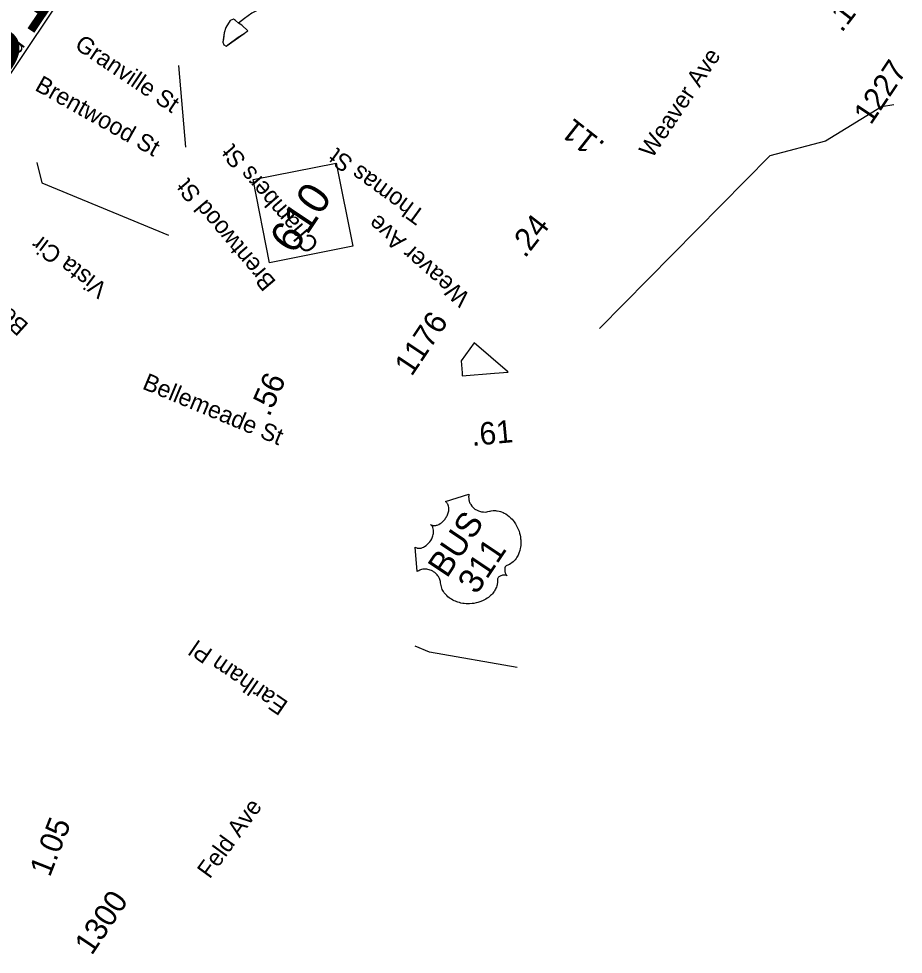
# Model space of a CAD drawing. Extents: x 1716282 to 1717158, y 799307 to 801078.
# Drawn here: x 1716976.7 to 1717048, y 800655.1 to 800730.5 of the extents above; entities that cross this region are included whole.
import ezdxf

# ---------------------------------------------------------------- set-up
doc = ezdxf.new("R2010")
doc.units = 0
for name, color, linetype in [('Exist Boundary Political City Limit New Hole', 7, 'Continuous'), ('Exist Hydrographic Misc Water Feature', 7, 'Continuous'), ('Exist Road Non-System Type 51', 7, 'Continuous'), ('Exist Road Non-System Type 51 Label', 7, 'Continuous'), ('Exist Road Primary Interstate Structure Ovrhead Sign CELL', 7, 'Continuous'), ('Exist Road Primary NC Mileage Hundredths English Label', 7, 'Continuous'), ('Exist Road Primary NC Shield CELL', 7, 'Continuous'), ('Exist Road Primary NC Shield Number Label', 7, 'Continuous'), ('Exist Road Primary US Mileage Hundredths English Label', 7, 'Continuous'), ('Exist Road Primary US Shield CELL', 7, 'Continuous'), ('Exist Road Primary US Shield Number Label', 7, 'Continuous'), ('Exist Road Secondary Mileage Hundredths English Label', 7, 'Continuous'), ('Exist Road Secondary Mileage Tenths English Label', 7, 'Continuous'), ('Exist Road Secondary Type 51 Number Label', 7, 'Continuous')]:
    doc.layers.add(name, color=color, linetype=linetype)

msp = doc.modelspace()

# ---------------------------------------------------------------- linework, layer by layer
at = {"layer": 'Exist Boundary Political City Limit New Hole'}
msp.add_lwpolyline([(1717015.061, 800701.907), (1717016.154, 800701.996), (1717016.081, 800702.06), (1717016.106, 800702.062), (1717013.44, 800704.375), (1717012.374, 800702.905), (1717012.452, 800701.95), (1717012.468, 800701.762), (1717012.474, 800701.693), (1717015.061, 800701.907)], dxfattribs=at)
at = {"layer": 'Exist Hydrographic Misc Water Feature'}
for points in [[(1717006.217, 800745.185), (1717005.764, 800744.265), (1717005.583, 800743.125), (1717005.671, 800742.431), (1717005.92, 800741.665), (1717005.861, 800740.651), (1717005.434, 800738.485), (1717005.165, 800737.473), (1717004.642, 800736.039), (1717003.846, 800734.719), (1717003.113, 800733.955), (1717002.245, 800733.25), (1717001.104, 800732.763), (1717000, 800732.535), (1716998.83, 800732.211), (1716997.53, 800731.798), (1716996.577, 800731.431), (1716995.525, 800730.92), (1716994.916, 800730.494), (1716994.446, 800730.111)], [(1716994.446, 800730.111), (1716994.198, 800730.316), (1716994.031, 800730.43), (1716993.78, 800730.321), (1716993.426, 800729.752), (1716993.279, 800729.329), (1716993.225, 800728.839), (1716993.189, 800728.58), (1716993.251, 800728.364), (1716993.459, 800728.256), (1716993.695, 800728.447), (1716994.408, 800728.977), (1716994.894, 800729.278), (1716995.041, 800729.389), (1716995.186, 800729.499), (1716994.709, 800729.933), (1716994.446, 800730.111)], [(1716994.446, 800730.111), (1716994.198, 800730.316), (1716994.031, 800730.43), (1716993.78, 800730.321), (1716993.426, 800729.752), (1716993.279, 800729.329), (1716993.189, 800728.58), (1716993.251, 800728.364), (1716993.459, 800728.256), (1716994.894, 800729.278), (1716995.041, 800729.389), (1716995.186, 800729.499), (1716994.709, 800729.933), (1716994.446, 800730.111)], [(1717047.219, 800723.53), (1717046.231, 800723.377), (1717041.732, 800720.594), (1717037.245, 800719.41), (1717023.521, 800705.511)], [(1717016.89, 800678.217), (1717009.828, 800679.448), (1717008.667, 800679.945)]]:
    msp.add_lwpolyline(points, dxfattribs=at)
at = {"layer": 'Exist Road Non-System Type 51'}
msp.add_line((1716990.19, 800720.107), (1716989.626, 800726.707), dxfattribs=at)
msp.add_lwpolyline([(1716978.192, 800718.887), (1716978.599, 800717.245), (1716988.819, 800713.026)], dxfattribs=at)
at = {"layer": 'Exist Road Primary Interstate Structure Ovrhead Sign CELL'}
msp.add_lwpolyline([(1716969.549, 800728.043), (1716984.84, 800750.889), (1716990.251, 800747.268), (1716974.959, 800724.421)], close=True, dxfattribs=at)
at = {"layer": 'Exist Road Primary NC Shield CELL'}
msp.add_lwpolyline([(1716996.945, 800710.811), (1716995.618, 800717.509), (1717002.316, 800718.836), (1717003.643, 800712.137)], close=True, dxfattribs=at)
at = {"layer": 'Exist Road Primary US Shield CELL'}
msp.add_lwpolyline([(1717008.682, 800687.905), (1717008.737, 800687.872), (1717008.809, 800687.843), (1717008.848, 800687.831), (1717008.93, 800687.819), (1717009.035, 800687.819), (1717009.153, 800687.838), (1717009.267, 800687.873), (1717009.334, 800687.902), (1717009.44, 800687.958), (1717009.548, 800688.029), (1717009.653, 800688.118), (1717009.751, 800688.216), (1717009.848, 800688.33), (1717009.931, 800688.45), (1717010.01, 800688.588), (1717010.079, 800688.752), (1717010.106, 800688.831), (1717010.131, 800688.923), (1717010.149, 800689.012), (1717010.159, 800689.116), (1717010.161, 800689.203), (1717010.158, 800689.275), (1717010.138, 800689.386), (1717010.107, 800689.485), (1717010.085, 800689.533), (1717010.061, 800689.577), (1717010.002, 800689.656), (1717009.973, 800689.686), (1717009.906, 800689.739), (1717009.968, 800689.704), (1717010.01, 800689.685), (1717010.052, 800689.67), (1717010.101, 800689.66), (1717010.174, 800689.651), (1717010.24, 800689.65), (1717010.345, 800689.662), (1717010.402, 800689.676), (1717010.45, 800689.69), (1717010.568, 800689.737), (1717010.688, 800689.805), (1717010.743, 800689.84), (1717010.796, 800689.879), (1717010.859, 800689.931), (1717010.92, 800689.988), (1717010.976, 800690.047), (1717011.031, 800690.108), (1717011.083, 800690.174), (1717011.123, 800690.23), (1717011.169, 800690.3), (1717011.208, 800690.367), (1717011.244, 800690.438), (1717011.281, 800690.518), (1717011.307, 800690.585), (1717011.338, 800690.676), (1717011.36, 800690.762), (1717011.374, 800690.841), (1717011.386, 800690.949), (1717011.389, 800691.04), (1717011.382, 800691.112), (1717011.368, 800691.202), (1717011.342, 800691.296), (1717011.318, 800691.357), (1717011.287, 800691.41), (1717011.252, 800691.463), (1717011.209, 800691.51), (1717011.169, 800691.546), (1717011.131, 800691.573), (1717013.009, 800692.17), (1717013, 800692.133), (1717012.987, 800692.04), (1717012.983, 800691.963), (1717012.986, 800691.834), (1717012.995, 800691.773), (1717013.005, 800691.711), (1717013.02, 800691.651), (1717013.035, 800691.597), (1717013.061, 800691.525), (1717013.091, 800691.458), (1717013.125, 800691.387), (1717013.159, 800691.33), (1717013.235, 800691.222), (1717013.288, 800691.16), (1717013.335, 800691.11), (1717013.439, 800691.019), (1717013.491, 800690.979), (1717013.545, 800690.943), (1717013.603, 800690.908), (1717013.661, 800690.877), (1717013.725, 800690.848), (1717013.781, 800690.824), (1717013.853, 800690.799), (1717013.939, 800690.774), (1717014.027, 800690.756), (1717014.177, 800690.74), (1717014.341, 800690.739), (1717014.441, 800690.75), (1717014.53, 800690.767), (1717014.65, 800690.801), (1717014.716, 800690.819), (1717014.798, 800690.835), (1717014.945, 800690.853), (1717015.011, 800690.856), (1717015.082, 800690.856), (1717015.153, 800690.852), (1717015.228, 800690.846), (1717015.292, 800690.838), (1717015.431, 800690.81), (1717015.56, 800690.771), (1717015.626, 800690.749), (1717015.768, 800690.689), (1717015.836, 800690.656), (1717015.965, 800690.584), (1717016.114, 800690.485), (1717016.247, 800690.38), (1717016.393, 800690.243), (1717016.477, 800690.156), (1717016.569, 800690.045), (1717016.646, 800689.947), (1717016.753, 800689.79), (1717016.824, 800689.668), (1717016.903, 800689.517), (1717016.947, 800689.421), (1717016.992, 800689.313), (1717017.039, 800689.184), (1717017.085, 800689.04), (1717017.125, 800688.876), (1717017.15, 800688.748), (1717017.173, 800688.589), (1717017.182, 800688.495), (1717017.19, 800688.365), (1717017.189, 800688.194), (1717017.179, 800688.033), (1717017.163, 800687.9), (1717017.142, 800687.787), (1717017.109, 800687.644), (1717017.035, 800687.42), (1717017.003, 800687.342), (1717016.961, 800687.252), (1717016.917, 800687.171), (1717016.872, 800687.094), (1717016.805, 800686.994), (1717016.732, 800686.9), (1717016.655, 800686.815), (1717016.569, 800686.731), (1717016.471, 800686.649), (1717016.372, 800686.581), (1717016.263, 800686.518), (1717016.058, 800686.427), (1717016.003, 800686.397), (1717015.979, 800686.376), (1717015.935, 800686.317), (1717015.908, 800686.251), (1717015.892, 800686.176), (1717015.887, 800686.128), (1717015.887, 800686.06), (1717015.891, 800686.004), (1717015.904, 800685.933), (1717015.918, 800685.879), (1717015.93, 800685.838), (1717015.97, 800685.746), (1717015.993, 800685.708), (1717016.025, 800685.663), (1717016.079, 800685.605), (1717015.985, 800685.639), (1717015.916, 800685.651), (1717015.853, 800685.654), (1717015.794, 800685.653), (1717015.712, 800685.642), (1717015.647, 800685.628), (1717015.575, 800685.606), (1717015.51, 800685.575), (1717015.461, 800685.548), (1717015.421, 800685.52), (1717015.379, 800685.482), (1717015.351, 800685.446), (1717015.331, 800685.414), (1717015.312, 800685.365), (1717015.315, 800685.279), (1717015.316, 800685.199), (1717015.313, 800685.114), (1717015.303, 800685.018), (1717015.293, 800684.95), (1717015.275, 800684.871), (1717015.251, 800684.783), (1717015.219, 800684.69), (1717015.18, 800684.599), (1717015.144, 800684.52), (1717015.1, 800684.439), (1717015.056, 800684.369), (1717015.007, 800684.297), (1717014.957, 800684.234), (1717014.898, 800684.16), (1717014.819, 800684.073), (1717014.747, 800684.005), (1717014.668, 800683.936), (1717014.582, 800683.867), (1717014.484, 800683.798), (1717014.356, 800683.715), (1717014.26, 800683.662), (1717014.101, 800683.583), (1717013.897, 800683.503), (1717013.73, 800683.451), (1717013.599, 800683.419), (1717013.394, 800683.38), (1717013.265, 800683.363), (1717013.045, 800683.347), (1717012.891, 800683.346), (1717012.783, 800683.351), (1717012.613, 800683.366), (1717012.51, 800683.381), (1717012.364, 800683.408), (1717012.235, 800683.44), (1717012.116, 800683.474), (1717012.041, 800683.499), (1717011.915, 800683.548), (1717011.828, 800683.585), (1717011.711, 800683.642), (1717011.593, 800683.71), (1717011.489, 800683.778), (1717011.404, 800683.838), (1717011.31, 800683.915), (1717011.215, 800684.004), (1717011.137, 800684.086), (1717011.083, 800684.148), (1717011.021, 800684.229), (1717010.957, 800684.324), (1717010.9, 800684.423), (1717010.857, 800684.511), (1717010.815, 800684.612), (1717010.784, 800684.705), (1717010.757, 800684.818), (1717010.738, 800684.93), (1717010.729, 800685.026), (1717010.706, 800685.149), (1717010.688, 800685.217), (1717010.657, 800685.304), (1717010.625, 800685.38), (1717010.595, 800685.443), (1717010.546, 800685.532), (1717010.505, 800685.593), (1717010.439, 800685.68), (1717010.388, 800685.735), (1717010.32, 800685.803), (1717010.254, 800685.862), (1717010.164, 800685.927), (1717010.087, 800685.975), (1717009.992, 800686.025), (1717009.896, 800686.065), (1717009.809, 800686.094), (1717009.703, 800686.119), (1717009.621, 800686.132), (1717009.504, 800686.139), (1717009.39, 800686.136), (1717009.289, 800686.123), (1717009.194, 800686.104), (1717009.115, 800686.078), (1717009.043, 800686.051), (1717008.96, 800686.012), (1717008.887, 800685.97), (1717008.845, 800685.941)], close=True, dxfattribs=at)

# ---------------------------------------------------------------- texts
at = {"layer": 'Exist Road Non-System Type 51 Label'}
for s, rotation, p in [('E Springfield Rd', 52.59426, (1716969.221, 800717.754)), ('Granville St', 326.2209, (1716981.163, 800728.121)), ('Weaver Ave', 56.20506, (1717027.763, 800719.163)), ('Brentwood St', 330.67743, (1716977.962, 800724.747)), ('Chambers St', 130.70328, (1717001.003, 800712.316)), ('Thomas St', 144.03532, (1717009.579, 800714.89)), ('Brentwood St', 130.29294, (1716997.528, 800709.284)), ('Weaver Ave', 138.59378, (1717013.18, 800708.163)), ('Bellemeade St', 137.87806, (1716977.62, 800705.837)), ('Vista Cir', 143.07536, (1716983.997, 800708.94)), ('Bellemeade St', 337.43529, (1716986.621, 800700.69)), ('Earlham Pl', 145.54388, (1716998.532, 800675.408)), ('Feld Ave', 53.9761, (1716992.125, 800661.137))]:
    msp.add_text(s, height=1.3775, rotation=rotation, dxfattribs=at).set_placement(p)
at = {"layer": 'Exist Road Primary Interstate Structure Ovrhead Sign CELL'}
msp.add_text('S1065', height=6.09, rotation=56.20506, dxfattribs=at).set_placement((1716974.636, 800724.301))
at = {"layer": 'Exist Road Primary NC Mileage Hundredths English Label'}
msp.add_text('.56', height=1.8125, rotation=66.11329, dxfattribs=at).set_placement((1716996.926, 800698.342))
at = {"layer": 'Exist Road Primary NC Shield Number Label'}
msp.add_text('610', height=2.5375, rotation=56.20506, dxfattribs=at).set_placement((1716998.906, 800711.402))
at = {"layer": 'Exist Road Primary US Mileage Hundredths English Label'}
msp.add_text('.61', height=1.8125, rotation=5.36049, dxfattribs=at).set_placement((1717013.265, 800696.053))
at = {"layer": 'Exist Road Primary US Shield Number Label'}
for s, p in [('BUS', (1717011.227, 800685.345)), ('311', (1717013.622, 800684.024))]:
    msp.add_text(s, height=1.9937, rotation=56.20506, dxfattribs=at).set_placement(p)
at = {"layer": 'Exist Road Secondary Mileage Hundredths English Label'}
for s, rotation, p in [('.11', 141.82402, (1717024.058, 800720.434)), ('.24', 52.17462, (1717017.52, 800711.122)), ('1.05', 68.46397, (1716979.244, 800661.278))]:
    msp.add_text(s, height=1.8125, rotation=rotation, dxfattribs=at).set_placement(p)
at = {"layer": 'Exist Road Secondary Mileage Tenths English Label'}
msp.add_text('.10', height=1.8125, rotation=52.48664, dxfattribs=at).set_placement((1717043.036, 800729.293))
at = {"layer": 'Exist Road Secondary Type 51 Number Label'}
for s, p in [('1227', (1717045.38, 800721.841)), ('1176', (1717008.392, 800701.592)), ('1300', (1716982.623, 800654.968))]:
    msp.add_text(s, height=1.8125, rotation=56.20506, dxfattribs=at).set_placement(p)

doc.saveas('drawing.dxf')
